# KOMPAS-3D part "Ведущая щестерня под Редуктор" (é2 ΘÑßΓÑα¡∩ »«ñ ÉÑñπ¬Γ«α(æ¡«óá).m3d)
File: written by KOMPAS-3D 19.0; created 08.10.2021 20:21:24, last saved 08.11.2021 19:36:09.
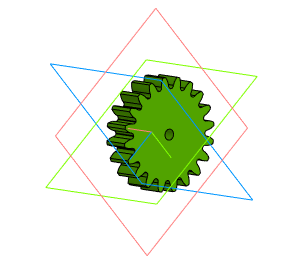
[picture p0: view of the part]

Document properties: Автор: Дымок(R); Организация: PDA-NN.3dn.ru; Полное имя файла: D:\3D_print\3D проекты Компас 3D\Редуктор (Снова)\В2 щестерня под Редуктор(Снова).m3d

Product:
- Part/product: Ведущая щестерня под Редуктор
    Материал: АБС 0603Т ТУ 2214-019-002 03521-96 (density 0 kg/m3)

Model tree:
1. ЛСК (Шестерня цилиндрическая с внешними зубьями):1  (with: Шестерня цилиндрическая с внешними зубьями:1, Плоскость XY, Плоскость ZX, Плоскость ZY, Ось X, Ось Y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)  (labels: &Фаска (Шестерня цилиндрическая с внешними зубьями):1)
     Ось X. X = 1; Ось Y. Y = 1; Ось Z. Z = 1; Угол 1 = 360
2. Эскиз для винтовой линии (Шестерня цилиндрическая с внешними зубьями):1  (with: Винтовая линия (Шестерня цилиндрическая с внешними зубьями):1, Шестерня цилиндрическая с внешними зубьями:1, Впадина прямая (Шестерня цилиндрическая с внешними зубьями):1, Впадина косая (Шестерня цилиндрическая с внешними зубьями):1, Массив впадин (Шестерня цилиндрическая с внешними зубьями):1)  (2 pattern instances)
     Число витков = 0.00742627; Смещение 2 = 8
3. Впадина прямая (Шестерня цилиндрическая с внешними зубьями):1  (with: Массив впадин (Шестерня цилиндрическая с внешними зубьями):1, Шестерня цилиндрическая с внешними зубьями:1)  (20 pattern instances)
     N 1 = 1; Шаг 1 = 1; Номер 1 = 1
4. Впадина косая (Шестерня цилиндрическая с внешними зубьями):1  (with: Винтовая линия (Шестерня цилиндрическая с внешними зубьями):1)
     N 1 = 1; Шаг 1 = 1; Номер 1 = 1
5. Шестерня цилиндрическая с внешними зубьями:1
6. Эскиз:5  (with: Цилиндр (Шестерня цилиндрическая с внешними зубьями):1)
7. Элемент выдавливания:3  (labels: АБС 0603Т ТУ 2214-019-002 03521-96)

Expressions: (VGExtS_1_z*VGExtS_1_M)/COSD(VGExtS_1_Beta); 360/VGExtS_1_z
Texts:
  SHAFT3D
  Количество отображаемых зубьев
  Угол наклона линии зубьев
  Шаг по кольцевому направлению
  (VGExtS_1_Beta>0)?(M_PI*VGExtS_1_z*VGExtS_1_M/SIND(VGExtS_1_Beta)):1000
  (VGExtS_1_Da<=0||VGExtS_1_Da>5e+7)?25:VGExtS_1_Da
  (VGExtS_1_H<=0||VGExtS_1_H>5e+7)?25:VGExtS_1_H
  VGExtS_1_zz<VGExtS_1_z?(VGExtS_1_zz+1):VGExtS_1_z
  (VGExtS_1_zz<=0||VGExtS_1==1)||(VGExtS_1_Beta>0)?1:0
  (VGExtS_1_zz<=0||VGExtS_1==1)||(VGExtS_1_Beta<=0)?1:0
  (VGExtS_1==1)||(VGExtS_1_Beta<=0)?1:0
